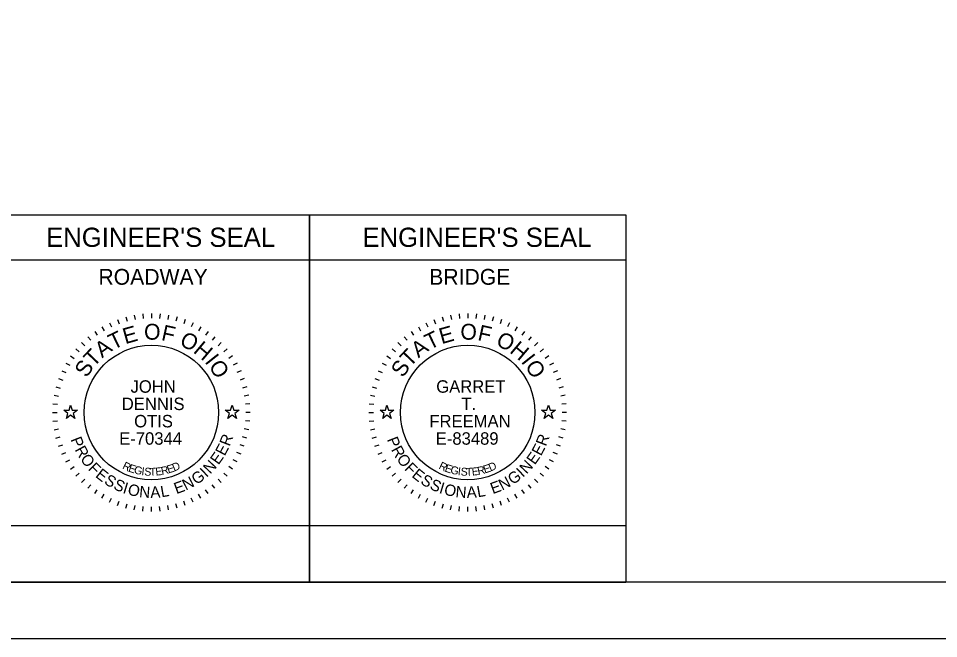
# Model space of a CAD drawing. Extents: x -11.1 to 43.5, y 0 to 22.
# Drawn here: x 23.82 to 31.97, y 0 to 5.49 of the extents above; entities that cross this region are included whole.
import ezdxf

# ---------------------------------------------------------------- set-up
doc = ezdxf.new("R2010")
doc.units = 0
for name, color, linetype in [('SH_Border', 7, 'Continuous'), ('SH_Cut_Line', 7, 'Continuous'), ('SH_Data', 7, 'Continuous'), ('SH_Seal', 7, 'Continuous')]:
    doc.layers.add(name, color=color, linetype=linetype)

msp = doc.modelspace()

# ---------------------------------------------------------------- linework, layer by layer
at = {"layer": 'SH_Border'}
msp.add_lwpolyline([(1.5, 21.5), (33.5, 21.5), (33.5, 0.5), (1.5, 0.5)], close=True, dxfattribs=at)
at = {"layer": 'SH_Cut_Line'}
msp.add_lwpolyline([(0, 0), (34, 0), (34, 22), (0, 22)], close=True, dxfattribs=at)
at = {"layer": 'SH_Data'}
for p, q in [((23.6, 3.75), (26.4, 3.75)), ((26.4, 3.75), (26.4, 0.5)), ((26.4, 0.5), (26.4, 3.75)), ((26.4, 0.5), (26.4, 3.75)), ((26.4, 3.75), (29.2, 3.75)), ((29.2, 3.75), (29.2, 0.5)), ((23.6, 3.35), (26.4, 3.35)), ((26.4, 3.35), (29.2, 3.35)), ((23.6, 0.5), (26.4, 0.5)), ((26.4, 0.5), (29.2, 0.5)), ((26.4, 0.5), (29.2, 0.5))]:
    msp.add_line(p, q, dxfattribs=at)
for points in [[(23.6, 0.5), (23.6, 1), (26.4, 1), (26.4, 0.5)], [(26.4, 0.5), (26.4, 1), (29.2, 1), (29.2, 0.5)], [(26.4, 0.5), (26.4, 1), (29.2, 1), (29.2, 0.5)]]:
    msp.add_lwpolyline(points, close=True, dxfattribs=at)
at = {"layer": 'SH_Seal'}
for p, q in [((24.8481, 2.8617), (24.855, 2.8223)), ((24.9237, 2.8717), (24.9272, 2.8318)), ((25, 2.875), (25, 2.835)), ((25.0763, 2.8717), (25.0728, 2.8318)), ((25.1519, 2.8617), (25.145, 2.8223)), ((27.6481, 2.8617), (27.655, 2.8223)), ((27.7237, 2.8717), (27.7272, 2.8318)), ((27.8, 2.875), (27.8, 2.835)), ((27.8763, 2.8717), (27.8728, 2.8318)), ((27.9519, 2.8617), (27.945, 2.8223)), ((24.6302, 2.793), (24.6471, 2.7568)), ((24.7007, 2.8222), (24.7144, 2.7846)), ((24.7735, 2.8452), (24.7839, 2.8065)), ((25.2265, 2.8452), (25.2161, 2.8065)), ((25.2993, 2.8222), (25.2856, 2.7846)), ((25.3698, 2.793), (25.3529, 2.7568)), ((27.4302, 2.793), (27.4471, 2.7568)), ((27.5007, 2.8222), (27.5144, 2.7846)), ((27.5735, 2.8452), (27.5839, 2.8065)), ((28.0265, 2.8452), (28.0161, 2.8065)), ((28.0993, 2.8222), (28.0856, 2.7846)), ((28.1698, 2.793), (28.1529, 2.7568)), ((24.4981, 2.7168), (24.5211, 2.684)), ((24.5625, 2.7578), (24.5825, 2.7231)), ((25.4375, 2.7578), (25.4175, 2.7231)), ((25.5019, 2.7168), (25.4789, 2.684)), ((27.2981, 2.7168), (27.3211, 2.684)), ((27.3625, 2.7578), (27.3825, 2.7231)), ((28.2375, 2.7578), (28.2175, 2.7231)), ((28.3019, 2.7168), (28.2789, 2.684)), ((24.3813, 2.6187), (24.4096, 2.5904)), ((24.4376, 2.6703), (24.4633, 2.6396)), ((25.5624, 2.6703), (25.5367, 2.6396)), ((25.6187, 2.6187), (25.5904, 2.5904)), ((27.1813, 2.6187), (27.2096, 2.5904)), ((27.2376, 2.6703), (27.2633, 2.6396)), ((28.3624, 2.6703), (28.3367, 2.6396)), ((28.4187, 2.6187), (28.3904, 2.5904)), ((24.3297, 2.5624), (24.3604, 2.5367)), ((25.6703, 2.5624), (25.6396, 2.5367)), ((27.1297, 2.5624), (27.1604, 2.5367)), ((28.4703, 2.5624), (28.4396, 2.5367)), ((24.2832, 2.5019), (24.316, 2.4789)), ((25.7168, 2.5019), (25.684, 2.4789)), ((27.0832, 2.5019), (27.116, 2.4789)), ((28.5168, 2.5019), (28.484, 2.4789)), ((24.207, 2.3698), (24.2432, 2.3529)), ((24.2422, 2.4375), (24.2769, 2.4175)), ((25.7578, 2.4375), (25.7231, 2.4175)), ((25.793, 2.3698), (25.7568, 2.3529)), ((27.007, 2.3698), (27.0432, 2.3529)), ((27.0422, 2.4375), (27.0769, 2.4175)), ((28.5578, 2.4375), (28.5231, 2.4175)), ((28.593, 2.3698), (28.5568, 2.3529)), ((24.1778, 2.2993), (24.2154, 2.2856)), ((25.8222, 2.2993), (25.7846, 2.2856)), ((26.9778, 2.2993), (27.0154, 2.2856)), ((28.6222, 2.2993), (28.5846, 2.2856)), ((24.1548, 2.2265), (24.1935, 2.2161)), ((25.8452, 2.2265), (25.8065, 2.2161)), ((26.9548, 2.2265), (26.9935, 2.2161)), ((28.6452, 2.2265), (28.6065, 2.2161)), ((24.1383, 2.1519), (24.1777, 2.145)), ((25.8617, 2.1519), (25.8223, 2.145)), ((26.9383, 2.1519), (26.9777, 2.145)), ((28.6617, 2.1519), (28.6223, 2.145)), ((24.1283, 2.0763), (24.1682, 2.0728)), ((25.8717, 2.0763), (25.8318, 2.0728)), ((26.9283, 2.0763), (26.9682, 2.0728)), ((28.6717, 2.0763), (28.6318, 2.0728)), ((24.125, 2), (24.165, 2)), ((25.875, 2), (25.835, 2)), ((26.925, 2), (26.965, 2)), ((28.675, 2), (28.635, 2)), ((24.1283, 1.9237), (24.1682, 1.9272)), ((25.8717, 1.9237), (25.8318, 1.9272)), ((26.9283, 1.9237), (26.9682, 1.9272)), ((28.6717, 1.9237), (28.6318, 1.9272)), ((24.1383, 1.8481), (24.1777, 1.855)), ((25.8617, 1.8481), (25.8223, 1.855)), ((26.9383, 1.8481), (26.9777, 1.855)), ((28.6617, 1.8481), (28.6223, 1.855)), ((24.1548, 1.7735), (24.1935, 1.7839)), ((24.1778, 1.7007), (24.2154, 1.7144)), ((25.8222, 1.7007), (25.7846, 1.7144)), ((25.8452, 1.7735), (25.8065, 1.7839)), ((26.9548, 1.7735), (26.9935, 1.7839)), ((26.9778, 1.7007), (27.0154, 1.7144)), ((28.6222, 1.7007), (28.5846, 1.7144)), ((28.6452, 1.7735), (28.6065, 1.7839)), ((24.207, 1.6302), (24.2432, 1.6471)), ((25.793, 1.6302), (25.7568, 1.6471)), ((27.007, 1.6302), (27.0432, 1.6471)), ((28.593, 1.6302), (28.5568, 1.6471)), ((24.2422, 1.5625), (24.2769, 1.5825)), ((25.7578, 1.5625), (25.7231, 1.5825)), ((27.0422, 1.5625), (27.0769, 1.5825)), ((28.5578, 1.5625), (28.5231, 1.5825)), ((24.2832, 1.4981), (24.316, 1.5211)), ((25.7168, 1.4981), (25.684, 1.5211)), ((27.0832, 1.4981), (27.116, 1.5211)), ((28.5168, 1.4981), (28.484, 1.5211)), ((24.3297, 1.4376), (24.3604, 1.4633)), ((24.3813, 1.3813), (24.4096, 1.4096)), ((25.6187, 1.3813), (25.5904, 1.4096)), ((25.6703, 1.4376), (25.6396, 1.4633)), ((27.1297, 1.4376), (27.1604, 1.4633)), ((27.1813, 1.3813), (27.2096, 1.4096)), ((28.4187, 1.3813), (28.3904, 1.4096)), ((28.4703, 1.4376), (28.4396, 1.4633)), ((24.4376, 1.3297), (24.4633, 1.3604)), ((24.4981, 1.2832), (24.5211, 1.316)), ((25.5019, 1.2832), (25.4789, 1.316)), ((25.5624, 1.3297), (25.5367, 1.3604)), ((27.2376, 1.3297), (27.2633, 1.3604)), ((27.2981, 1.2832), (27.3211, 1.316)), ((28.3019, 1.2832), (28.2789, 1.316)), ((28.3624, 1.3297), (28.3367, 1.3604)), ((24.5625, 1.2422), (24.5825, 1.2769)), ((24.6302, 1.207), (24.6471, 1.2432)), ((25.3698, 1.207), (25.3529, 1.2432)), ((25.4375, 1.2422), (25.4175, 1.2769)), ((27.3625, 1.2422), (27.3825, 1.2769)), ((27.4302, 1.207), (27.4471, 1.2432)), ((28.1698, 1.207), (28.1529, 1.2432)), ((28.2375, 1.2422), (28.2175, 1.2769)), ((24.7007, 1.1778), (24.7144, 1.2154)), ((24.7735, 1.1548), (24.7839, 1.1935)), ((24.8481, 1.1383), (24.855, 1.1777)), ((24.9237, 1.1283), (24.9272, 1.1682)), ((25, 1.125), (25, 1.165)), ((25.0763, 1.1283), (25.0728, 1.1682)), ((25.1519, 1.1383), (25.145, 1.1777)), ((25.2265, 1.1548), (25.2161, 1.1935)), ((25.2993, 1.1778), (25.2856, 1.2154)), ((27.5007, 1.1778), (27.5144, 1.2154)), ((27.5735, 1.1548), (27.5839, 1.1935)), ((27.6481, 1.1383), (27.655, 1.1777)), ((27.7237, 1.1283), (27.7272, 1.1682)), ((27.8, 1.125), (27.8, 1.165)), ((27.8763, 1.1283), (27.8728, 1.1682)), ((27.9519, 1.1383), (27.945, 1.1777)), ((28.0265, 1.1548), (28.0161, 1.1935)), ((28.0993, 1.1778), (28.0856, 1.2154))]:
    msp.add_line(p, q, dxfattribs=at)
for points in [[(24.2236, 2.02), (24.2705, 2.02), (24.285, 2.0645), (24.2995, 2.02), (24.3464, 2.02), (24.3085, 1.9924), (24.323, 1.9478), (24.285, 1.9754), (24.247, 1.9478), (24.2615, 1.9924)], [(25.6536, 2.02), (25.7005, 2.02), (25.715, 2.0645), (25.7295, 2.02), (25.7764, 2.02), (25.7385, 1.9924), (25.753, 1.9478), (25.715, 1.9754), (25.677, 1.9478), (25.6915, 1.9924)], [(27.0236, 2.02), (27.0705, 2.02), (27.085, 2.0645), (27.0995, 2.02), (27.1464, 2.02), (27.1085, 1.9924), (27.123, 1.9478), (27.085, 1.9754), (27.047, 1.9478), (27.0615, 1.9924)], [(28.4536, 2.02), (28.5005, 2.02), (28.515, 2.0645), (28.5295, 2.02), (28.5764, 2.02), (28.5385, 1.9924), (28.553, 1.9478), (28.515, 1.9754), (28.477, 1.9478), (28.4915, 1.9924)]]:
    msp.add_lwpolyline(points, close=True, dxfattribs=at)
for centre in [(25, 2), (27.8, 2)]:
    msp.add_circle(centre, 0.595, dxfattribs=at)

# ---------------------------------------------------------------- texts
at = {"layer": 'SH_Data'}
for s, height, p in [("ENGINEER'S SEAL", 0.17, (24.0676, 3.465)), ("ENGINEER'S SEAL", 0.17, (26.8676, 3.465)), ('ROADWAY', 0.14, (24.5311, 3.13)), ('BRIDGE', 0.14, (27.459, 3.13))]:
    msp.add_text(s, height=height, dxfattribs=at).set_placement(p)
at = {"layer": 'SH_Seal'}
for s, height, rotation, p in [('E', 0.14, 15.75706, (24.7684, 2.6038)), ('O', 0.14, 359.78119, (24.9347, 2.6443)), ('F', 0.14, 347.43619, (25.0811, 2.6417)), ('E', 0.14, 15.75706, (27.5684, 2.6038)), ('O', 0.14, 359.78119, (27.7347, 2.6443)), ('F', 0.14, 347.43619, (27.8811, 2.6417)), ('T', 0.14, 25.71674, (24.6616, 2.5518)), ('O', 0.14, 332.25863, (25.2398, 2.6015)), ('T', 0.14, 25.71674, (27.4616, 2.5518)), ('O', 0.14, 332.25863, (28.0398, 2.6015)), ('A', 0.14, 36.47472, (24.5634, 2.4781)), ('H', 0.14, 319.91363, (25.3632, 2.5361)), ('A', 0.14, 36.47472, (27.3634, 2.4781)), ('H', 0.14, 319.91363, (28.1632, 2.5361)), ('T', 0.14, 46.4344, (24.4883, 2.3964)), ('T', 0.14, 46.4344, (27.2883, 2.3964)), ('S', 0.14, 57.19238, (24.4281, 2.3014)), ('I', 0.14, 308.36695, (25.4665, 2.4483)), ('O', 0.14, 303.14906, (25.5021, 2.4089)), ('S', 0.14, 57.19238, (27.2281, 2.3014)), ('I', 0.14, 308.36695, (28.2665, 2.4483)), ('O', 0.14, 303.14906, (28.3021, 2.4089)), ('R', 0.1, 69.23216, (25.6919, 1.6954)), ('R', 0.1, 69.23216, (28.4919, 1.6954)), ('P', 0.1, 291.49398, (24.2823, 1.7621)), ('E', 0.1, 61.99508, (25.6476, 1.6098)), ('P', 0.1, 291.49398, (27.0823, 1.7621)), ('E', 0.1, 61.99508, (28.4476, 1.6098)), ('R', 0.1, 298.73106, (24.319, 1.6717)), ('E', 0.1, 54.75801, (25.5933, 1.5314)), ('R', 0.1, 298.73106, (27.119, 1.6717)), ('E', 0.1, 54.75801, (28.3933, 1.5314)), ('O', 0.1, 306.46664, (24.3655, 1.5883)), ('F', 0.1, 314.7068, (24.4343, 1.4983)), ('R', 0.07, 334.48695, (24.7375, 1.5051)), ('D', 0.07, 23.30524, (25.201, 1.477)), ('N', 0.1, 47.02243, (25.5202, 1.4508)), ('O', 0.1, 306.46664, (27.1655, 1.5883)), ('F', 0.1, 314.7068, (27.2343, 1.4983)), ('R', 0.07, 334.48695, (27.5375, 1.5051)), ('D', 0.07, 23.30524, (28.001, 1.477)), ('N', 0.1, 47.02243, (28.3202, 1.4508)), ('E', 0.1, 321.43929, (24.4978, 1.4348)), ('E', 0.07, 341.03996, (24.7906, 1.4801)), ('G', 0.07, 347.47515, (24.8414, 1.4618)), ('I', 0.07, 353.78581, (24.9091, 1.4468)), ('S', 0.07, 356.89262, (24.9358, 1.4429)), ('T', 0.07, 3.00609, (24.9857, 1.4387)), ('E', 0.07, 6.01169, (25.0389, 1.4412)), ('R', 0.07, 11.91844, (25.0925, 1.4474)), ('E', 0.07, 17.68363, (25.1498, 1.4602)), ('G', 0.1, 35.04687, (25.3981, 1.357)), ('I', 0.1, 43.28703, (25.4868, 1.4214)), ('E', 0.1, 321.43929, (27.2978, 1.4348)), ('E', 0.07, 341.03996, (27.5906, 1.4801)), ('G', 0.07, 347.47515, (27.6414, 1.4618)), ('I', 0.07, 353.78581, (27.7091, 1.4468)), ('S', 0.07, 356.89262, (27.7358, 1.4429)), ('T', 0.07, 3.00609, (27.7857, 1.4387)), ('E', 0.07, 6.01169, (27.8389, 1.4412)), ('R', 0.07, 11.91844, (27.8925, 1.4474)), ('E', 0.07, 17.68363, (27.9498, 1.4602)), ('G', 0.1, 35.04687, (28.1981, 1.357)), ('I', 0.1, 43.28703, (28.2868, 1.4214)), ('S', 0.1, 328.67637, (24.5743, 1.3752)), ('S', 0.1, 335.91345, (24.6564, 1.3266)), ('E', 0.1, 20.07421, (25.2212, 1.277)), ('N', 0.1, 27.31129, (25.3045, 1.3075)), ('S', 0.1, 328.67637, (27.3743, 1.3752)), ('S', 0.1, 335.91345, (27.4564, 1.3266)), ('E', 0.1, 20.07421, (28.0212, 1.277)), ('N', 0.1, 27.31129, (28.1045, 1.3075)), ('I', 0.1, 343.15053, (24.7406, 1.2897)), ('O', 0.1, 346.88592, (24.7839, 1.2751)), ('N', 0.1, 355.12608, (24.8888, 1.2517)), ('A', 0.1, 2.86166, (24.9923, 1.2437)), ('L', 0.1, 10.09874, (25.0894, 1.249)), ('I', 0.1, 343.15053, (27.5406, 1.2897)), ('O', 0.1, 346.88592, (27.5839, 1.2751)), ('N', 0.1, 355.12608, (27.6888, 1.2517)), ('A', 0.1, 2.86166, (27.7923, 1.2437)), ('L', 0.1, 10.09874, (27.8894, 1.249))]:
    msp.add_text(s, height=height, rotation=rotation, dxfattribs=at).set_placement(p)
for s, p in [('JOHN', (24.8153, 2.1749)), ('GARRET', (27.521, 2.1749)), ('DENNIS', (24.7376, 2.0216)), ('T.', (27.7439, 2.0216)), ('OTIS', (24.8471, 1.8684)), ('FREEMAN', (27.46, 1.8684)), ('E-70344', (24.7145, 1.7151)), ('E-83489', (27.5166, 1.7151))]:
    msp.add_text(s, height=0.11, dxfattribs=at).set_placement(p)

doc.saveas('drawing.dxf')
